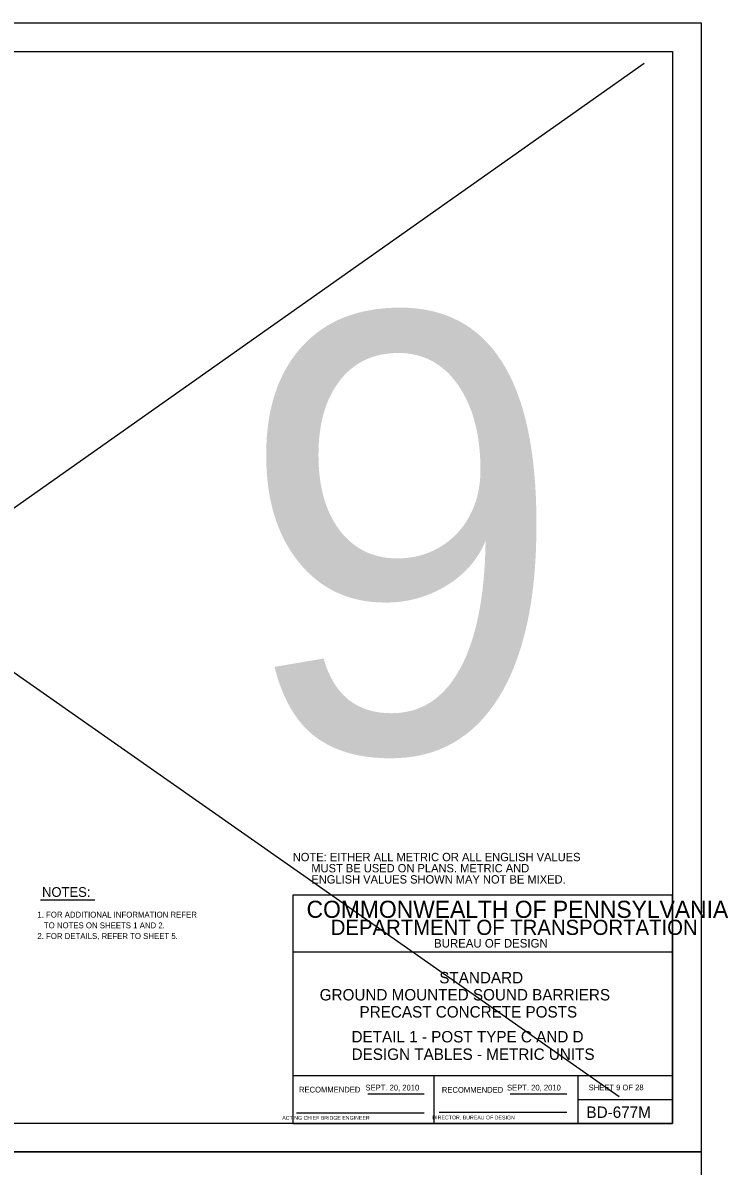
# Model space of a CAD drawing. Extents: x 3351 to 8430, y -3586 to 1457.
# Drawn here: x 7609 to 7981, y -624 to -22 of the extents above; entities that cross this region are included whole.
import ezdxf

# ---------------------------------------------------------------- set-up
doc = ezdxf.new("R2010")
doc.units = 0
for name, color, linetype in [('1', 7, 'Continuous'), ('2', 7, 'Continuous'), ('PLT-BNDY', 7, 'Continuous')]:
    doc.layers.add(name, color=color, linetype=linetype)

msp = doc.modelspace()

# ---------------------------------------------------------------- linework, layer by layer
at = {"layer": '1'}
for p, q in [((7150.02, -45.82), (7923.18, -587.15)), ((7936.43, -43.67), (7159.05, -591.55)), ((7618.47, -483.77), (7647.04, -483.77))]:
    msp.add_line(p, q, dxfattribs=at)
at = {"layer": '2'}
for p, q in [((7165.34, -37.31), (7951.34, -37.31)), ((7951.34, -37.31), (7951.34, -601.31)), ((7951.34, -481.31), (7751.34, -481.31)), ((7751.34, -481.31), (7751.34, -601.31)), ((7951.34, -601.31), (7951.34, -481.31)), ((7951.34, -511.31), (7751.34, -511.31)), ((7951.34, -576.31), (7751.34, -576.31)), ((7825.84, -601.31), (7825.84, -576.31)), ((7901.34, -576.31), (7901.34, -601.31)), ((7790.81, -585.81), (7820.57, -585.81)), ((7865.81, -585.81), (7895.71, -585.81)), ((7901.34, -588.81), (7951.34, -588.81)), ((7828.47, -595.43), (7895.71, -595.43)), ((7951.34, -601.31), (7165.34, -601.31)), ((7751.34, -601.31), (7951.34, -601.31)), ((7753.34, -595.81), (7820.57, -595.81))]:
    msp.add_line(p, q, dxfattribs=at)
at = {"layer": 'PLT-BNDY'}
for points in [[(7125.34, -22.31), (7966.34, -22.31), (7966.34, -616.31), (7125.34, -616.31)], [(7125.34, -616.31), (7966.34, -616.31), (7966.34, -1210.31), (7125.34, -1210.31)]]:
    msp.add_lwpolyline(points, close=True, dxfattribs=at)

# ---------------------------------------------------------------- texts
at = {"layer": '1'}
for s, height, p in [('9', 230.4, (7722.89, -405.96)), ('NOTES:', 5.117, (7619.31, -482.15)), ('1. FOR ADDITIONAL INFORMATION REFER', 3.072, (7616.86, -493.03)), ('   TO NOTES ON SHEETS 1 AND 2.', 3.072, (7616.86, -498.66)), ('2. FOR DETAILS, REFER TO SHEET 5.', 3.072, (7616.86, -504.29)), ('STANDARD', 6, (7828.48, -527.64)), ('GROUND MOUNTED SOUND BARRIERS', 6, (7765.5, -536.64)), ('PRECAST CONCRETE POSTS', 6, (7786.5, -545.64)), ('DETAIL 1 - POST TYPE C AND D', 6, (7782.29, -558.71)), ('DESIGN TABLES - METRIC UNITS', 6, (7782.31, -567.91)), ('SHEET 9 OF 28', 3, (7907.09, -583.92)), ('BD-677M', 6, (7905.97, -598.43))]:
    msp.add_text(s, height=height, dxfattribs=at).set_placement(p)
at = {"layer": '2'}
for s, height, p in [('NOTE: EITHER ALL METRIC OR ALL ENGLISH VALUES', 4.375, (7751.34, -463.37)), ('      MUST BE USED ON PLANS. METRIC AND', 4.375, (7751.34, -469.24)), ('      ENGLISH VALUES SHOWN MAY NOT BE MIXED.', 4.375, (7751.34, -475.12)), ('COMMONWEALTH OF PENNSYLVANIA', 9, (7758.59, -493.18)), ('DEPARTMENT OF TRANSPORTATION', 8.0002, (7771.34, -502.18)), ('BUREAU OF DESIGN', 4.5, (7825.72, -508.81)), ('SEPT. 20, 2010', 3, (7789.61, -584)), ('       ACTING CHIEF BRIDGE ENGINEER', 2.0002, (7740.43, -599.43))]:
    msp.add_text(s, height=height, dxfattribs=at).set_placement(p)
for s, height, p in [('RECOMMENDED', 3, (7754.61, -585.06)), ('RECOMMENDED', 3, (7829.83, -585.18)), ('SEPT. 20, 2010', 3, (7864.16, -584)), ('   DIRECTOR, BUREAU OF DESIGN', 2.0002, (7822.54, -599.25))]:
    msp.add_text(s, height=height, rotation=360, dxfattribs=at).set_placement(p)

doc.saveas('drawing.dxf')
